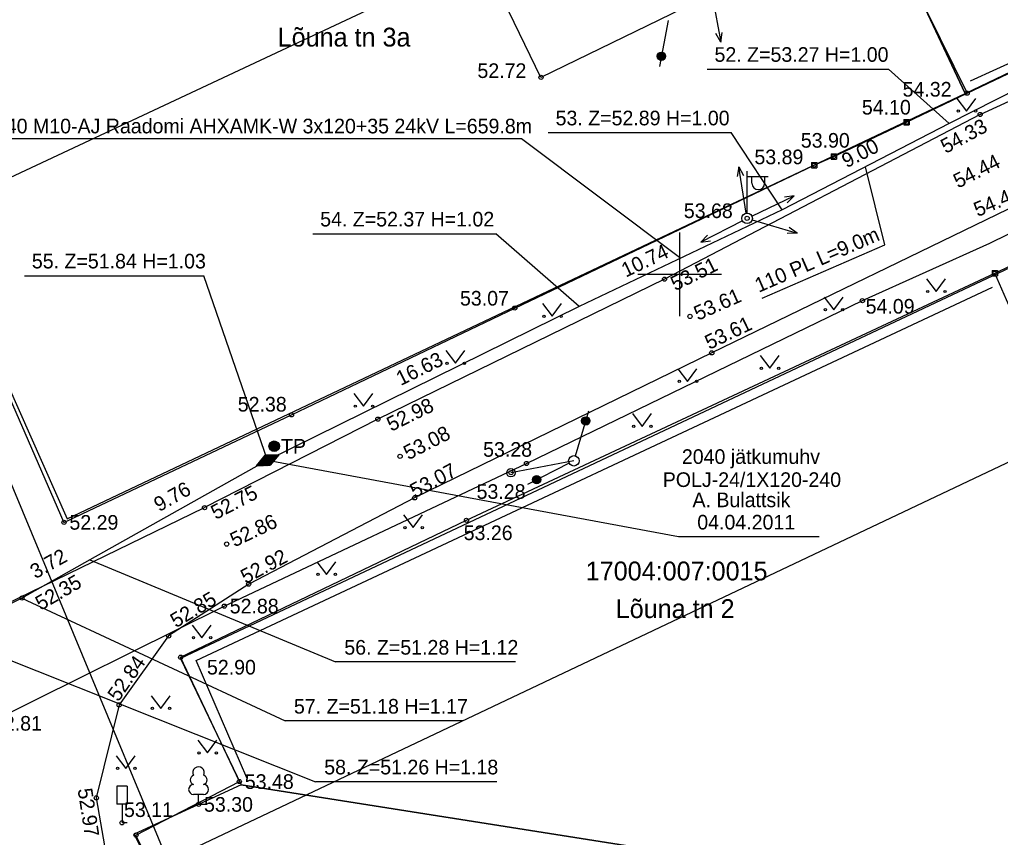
# Model space of a CAD drawing. Extents: x 642747 to 644424, y 6457048 to 6458238.
# Drawn here: x 643818.42 to 643865.35, y 6457573.06 to 6457612.18 of the extents above; entities that cross this region are included whole.
import ezdxf

# ---------------------------------------------------------------- set-up
doc = ezdxf.new("R2010")
doc.units = 0
for name, color, linetype in [('ABIJOONIS', 7, 'Continuous'), ('AED', 7, 'Continuous'), ('HALJASTUS', 7, 'Continuous'), ('HOONE', 7, 'Continuous'), ('JOONSIDE', 7, 'Continuous'), ('KOORDPUNKT', 7, 'Continuous'), ('KORGUS', 7, 'Continuous'), ('KPKAABEL', 7, 'Continuous'), ('KTRASS', 7, 'Continuous'), ('LIIKLUS', 7, 'Continuous'), ('MOOTPIIR', 7, 'Continuous'), ('MPOHULIIN', 7, 'Continuous'), ('PIIR', 7, 'Continuous'), ('POST', 7, 'Continuous'), ('PUU', 7, 'Continuous'), ('SIOHULIIN', 7, 'Continuous'), ('SITRASS', 7, 'Continuous'), ('TEE', 7, 'Continuous'), ('VORK', 7, 'Continuous')]:
    doc.layers.add(name, color=color, linetype=linetype)

msp = doc.modelspace()

# ---------------------------------------------------------------- linework, layer by layer
at = {"layer": 'ABIJOONIS'}
for points in [[(643816.733, 6457606.496), (643842.433, 6457606.496), (643850.05, 6457600.77)], [(643853.945, 6457598.849), (643859.815, 6457601.408), (643858.899, 6457605.144)], [(643830.279, 6457591.107), (643849.945, 6457587.448), (643856.673, 6457587.448)]]:
    msp.add_lwpolyline(points, dxfattribs=at)
at = {"layer": 'AED'}
for p, q in [((643860.735, 6457607.395), (643860.735, 6457607.145)), ((643860.735, 6457607.395), (643860.985, 6457607.395)), ((643860.735, 6457607.145), (643860.985, 6457607.145)), ((643860.985, 6457607.395), (643860.985, 6457607.145)), ((643857.252, 6457605.76), (643857.252, 6457605.51)), ((643857.252, 6457605.76), (643857.502, 6457605.76)), ((643857.502, 6457605.76), (643857.502, 6457605.51)), ((643856.314, 6457605.342), (643856.314, 6457605.092)), ((643856.314, 6457605.342), (643856.564, 6457605.342)), ((643856.314, 6457605.092), (643856.564, 6457605.092)), ((643856.564, 6457605.342), (643856.564, 6457605.092)), ((643857.252, 6457605.51), (643857.502, 6457605.51)), ((643864.958, 6457600.176), (643864.958, 6457599.926)), ((643864.958, 6457600.176), (643865.208, 6457600.176)), ((643864.958, 6457599.926), (643865.208, 6457599.926)), ((643867.365, 6457594.799), (643865.083, 6457600.051)), ((643865.208, 6457600.176), (643865.208, 6457599.926))]:
    msp.add_line(p, q, dxfattribs=at)
for points in [[(643861.822, 6457612.574), (643863.757, 6457608.659), (643878.812, 6457615.836), (643879.918, 6457616.353), (643883.479, 6457617.962)], [(643865.083, 6457600.051), (643868.028, 6457601.433), (643891.175, 6457612.475), (643903.211, 6457617.963)], [(643813.028, 6457615.84), (643810.323, 6457611.698), (643815.123, 6457600.51), (643820.539, 6457588.129), (643831.427, 6457593.27), (643842.111, 6457598.383), (643856.439, 6457605.217), (643857.377, 6457605.635), (643860.86, 6457607.27), (643863.757, 6457608.659)], [(643828.932, 6457575.729), (643826.121, 6457581.679), (643839.798, 6457588.228), (643865.083, 6457600.051)], [(643829.938, 6457561.161), (643823.985, 6457573.169), (643828.932, 6457575.729)]]:
    msp.add_lwpolyline(points, dxfattribs=at)
at = {"layer": 'HALJASTUS'}
for p, q in [((643878.552, 6457615.933), (643863.897, 6457609.235)), ((643863.27, 6457608.411), (643863.733, 6457607.804)), ((643863.733, 6457607.804), (643864.179, 6457608.411)), ((643861.809, 6457599.78), (643862.272, 6457599.173)), ((643862.272, 6457599.173), (643862.718, 6457599.78)), ((643843.441, 6457598.594), (643843.905, 6457597.987)), ((643843.905, 6457597.987), (643844.35, 6457598.594)), ((643856.915, 6457598.908), (643857.378, 6457598.301)), ((643857.378, 6457598.301), (643857.824, 6457598.908)), ((643838.809, 6457596.348), (643839.273, 6457595.741)), ((643839.273, 6457595.741), (643839.718, 6457596.348)), ((643853.855, 6457596.111), (643854.318, 6457595.504)), ((643854.318, 6457595.504), (643854.764, 6457596.111)), ((643849.921, 6457595.477), (643850.384, 6457594.871)), ((643850.384, 6457594.871), (643850.83, 6457595.477)), ((643834.416, 6457594.293), (643834.879, 6457593.687)), ((643834.879, 6457593.687), (643835.325, 6457594.293)), ((643847.739, 6457593.329), (643848.202, 6457592.722)), ((643848.202, 6457592.722), (643848.648, 6457593.329)), ((643836.792, 6457588.488), (643837.255, 6457587.881)), ((643837.255, 6457587.881), (643837.701, 6457588.488)), ((643832.637, 6457586.242), (643833.1, 6457585.636)), ((643833.1, 6457585.636), (643833.546, 6457586.242)), ((643826.673, 6457583.219), (643827.137, 6457582.612)), ((643827.137, 6457582.612), (643827.582, 6457583.219)), ((643824.705, 6457579.835), (643825.168, 6457579.228)), ((643825.168, 6457579.228), (643825.614, 6457579.835)), ((643826.943, 6457577.705), (643827.406, 6457577.098)), ((643827.406, 6457577.098), (643827.852, 6457577.705)), ((643823.041, 6457576.968), (643823.504, 6457576.361)), ((643823.504, 6457576.361), (643823.95, 6457576.968))]:
    msp.add_line(p, q, dxfattribs=at)
msp.add_lwpolyline([(643829.285, 6457575.914), (643826.869, 6457581.513), (643864.976, 6457599.384)], dxfattribs=at)
for centre in [(643863.332, 6457607.804), (643864.161, 6457607.804), (643861.871, 6457599.173), (643862.7, 6457599.173), (643843.503, 6457597.987), (643844.332, 6457597.987), (643856.977, 6457598.301), (643857.806, 6457598.301), (643838.871, 6457595.741), (643839.7, 6457595.741), (643853.917, 6457595.504), (643854.746, 6457595.504), (643849.983, 6457594.871), (643850.812, 6457594.871), (643834.478, 6457593.687), (643835.307, 6457593.687), (643847.801, 6457592.722), (643848.63, 6457592.722), (643836.854, 6457587.881), (643837.683, 6457587.881), (643832.699, 6457585.636), (643833.528, 6457585.636), (643826.736, 6457582.612), (643827.564, 6457582.612), (643824.767, 6457579.228), (643825.596, 6457579.228), (643827.005, 6457577.098), (643827.834, 6457577.098), (643823.103, 6457576.361), (643823.932, 6457576.361)]:
    msp.add_circle(centre, 0.055, dxfattribs=at)
at = {"layer": 'HOONE'}
msp.add_lwpolyline([(643852.233, 6457621.198), (643853.69, 6457618.146), (643850.68, 6457616.709), (643852.137, 6457613.657), (643850.16, 6457612.713), (643843.365, 6457609.415), (643841.578, 6457613.097)], dxfattribs=at)
at = {"layer": 'KOORDPUNKT'}
for p, q in [((643851.319, 6457609.811), (643859.998, 6457609.811)), ((643862.896, 6457607.211), (643859.998, 6457609.811)), ((643843.714, 6457606.772), (643852.463, 6457606.772)), ((643854.902, 6457603.076), (643852.463, 6457606.772)), ((643832.449, 6457601.934), (643841.198, 6457601.934)), ((643845.198, 6457598.463), (643841.198, 6457601.934)), ((643818.652, 6457599.927), (643827.227, 6457599.927)), ((643830.279, 6457591.107), (643827.227, 6457599.927)), ((643821.771, 6457586.329), (643833.533, 6457581.451)), ((643818.529, 6457584.508), (643831.123, 6457578.631)), ((643814.969, 6457582.717), (643832.573, 6457575.723)), ((643842.142, 6457581.451), (643833.533, 6457581.451)), ((643839.628, 6457578.631), (643831.123, 6457578.631)), ((643841.253, 6457575.723), (643832.573, 6457575.723))]:
    msp.add_line(p, q, dxfattribs=at)
for points in [[(643862.896, 6457607.211), (643862.896, 6457607.211), (643862.896, 6457607.211)], [(643854.902, 6457603.076), (643854.902, 6457603.076), (643854.902, 6457603.076)], [(643845.198, 6457598.463), (643845.198, 6457598.463), (643845.198, 6457598.463)], [(643830.279, 6457591.107), (643830.279, 6457591.107), (643830.279, 6457591.107)], [(643821.771, 6457586.329), (643821.771, 6457586.329), (643821.771, 6457586.329)], [(643818.529, 6457584.508), (643818.529, 6457584.508), (643818.529, 6457584.508)]]:
    msp.add_lwpolyline(points, dxfattribs=at)
at = {"layer": 'KORGUS'}
for centre in [(643843.365, 6457609.415), (643863.757, 6457608.659), (643864.382, 6457607.643), (643860.86, 6457607.27), (643857.377, 6457605.635), (643856.439, 6457605.217), (643853.23, 6457602.673), (643865.083, 6457600.051), (643849.276, 6457599.763), (643858.747, 6457598.735), (643842.111, 6457598.383), (643850.497, 6457597.981), (643851.537, 6457596.237), (643831.427, 6457593.27), (643835.56, 6457593.069), (643836.623, 6457591.289), (643842.673, 6457590.948), (643841.927, 6457590.503), (643837.319, 6457589.3), (643827.265, 6457588.833), (643820.539, 6457588.129), (643839.798, 6457588.228), (643828.324, 6457587.09), (643829.38, 6457585.174), (643818.529, 6457584.508), (643828.211, 6457584.123), (643825.548, 6457582.694), (643826.121, 6457581.679), (643823.177, 6457579.399), (643828.932, 6457575.729), (643822.086, 6457574.949), (643826.98, 6457574.637), (643823.317, 6457573.755), (643823.985, 6457573.169)]:
    msp.add_circle(centre, 0.1, dxfattribs=at)
at = {"layer": 'KPKAABEL'}
for p, q in [((643829.747, 6457590.841), (643830.16, 6457591.348)), ((643829.876, 6457591), (643830.077, 6457590.851)), ((643829.892, 6457591.019), (643830.118, 6457590.853)), ((643829.908, 6457591.039), (643830.159, 6457590.854)), ((643829.924, 6457591.058), (643830.199, 6457590.855)), ((643829.939, 6457591.077), (643830.24, 6457590.856)), ((643829.955, 6457591.097), (643830.28, 6457590.857)), ((643829.971, 6457591.116), (643830.321, 6457590.859)), ((643829.987, 6457591.135), (643830.361, 6457590.86)), ((643830.003, 6457591.155), (643830.4, 6457590.862)), ((643830.019, 6457591.174), (643830.416, 6457590.881)), ((643830.034, 6457591.194), (643830.432, 6457590.901)), ((643830.05, 6457591.213), (643830.448, 6457590.92)), ((643830.066, 6457591.232), (643830.464, 6457590.939)), ((643830.082, 6457591.252), (643830.48, 6457590.959)), ((643830.098, 6457591.271), (643830.495, 6457590.978)), ((643830.113, 6457591.291), (643830.511, 6457590.998)), ((643830.129, 6457591.31), (643830.527, 6457591.017)), ((643830.145, 6457591.329), (643830.543, 6457591.036)), ((643830.813, 6457591.367), (643830.16, 6457591.348)), ((643830.163, 6457591.348), (643830.559, 6457591.056)), ((643830.203, 6457591.349), (643830.575, 6457591.075)), ((643830.244, 6457591.35), (643830.59, 6457591.095)), ((643830.284, 6457591.351), (643830.606, 6457591.114)), ((643830.325, 6457591.352), (643830.622, 6457591.133)), ((643830.365, 6457591.354), (643830.638, 6457591.153)), ((643830.813, 6457591.367), (643830.4, 6457590.861)), ((643830.406, 6457591.355), (643830.654, 6457591.172)), ((643830.446, 6457591.356), (643830.67, 6457591.192)), ((643830.487, 6457591.357), (643830.685, 6457591.211)), ((643830.527, 6457591.359), (643830.701, 6457591.23)), ((643830.568, 6457591.36), (643830.717, 6457591.25)), ((643830.608, 6457591.361), (643830.733, 6457591.269)), ((643830.649, 6457591.362), (643830.749, 6457591.288)), ((643830.689, 6457591.363), (643830.764, 6457591.308)), ((643830.73, 6457591.365), (643830.78, 6457591.327)), ((643830.77, 6457591.366), (643830.796, 6457591.347)), ((643830.811, 6457591.367), (643830.812, 6457591.366)), ((643829.747, 6457590.841), (643830.4, 6457590.861)), ((643829.765, 6457590.864), (643829.794, 6457590.843)), ((643829.781, 6457590.883), (643829.834, 6457590.844)), ((643829.797, 6457590.903), (643829.875, 6457590.845)), ((643829.813, 6457590.922), (643829.915, 6457590.847)), ((643829.829, 6457590.942), (643829.956, 6457590.848)), ((643829.844, 6457590.961), (643829.996, 6457590.849)), ((643829.86, 6457590.98), (643830.037, 6457590.85))]:
    msp.add_line(p, q, dxfattribs=at)
for points in [[(643871.792, 6457611.727), (643862.896, 6457607.211), (643854.902, 6457603.076), (643845.198, 6457598.463), (643830.279, 6457591.107), (643821.771, 6457586.329), (643818.529, 6457584.508), (643814.969, 6457582.717), (643809.094, 6457580.741), (643805.91, 6457580.287), (643796.342, 6457575.552), (643785.796, 6457571.037), (643776.843, 6457566.645)], [(643862.896, 6457607.211), (643854.902, 6457603.076)], [(643821.771, 6457586.329), (643818.529, 6457584.508), (643814.969, 6457582.717), (643809.094, 6457580.741), (643805.91, 6457580.287)]]:
    msp.add_lwpolyline(points, dxfattribs=at)
at = {"layer": 'KTRASS'}
msp.add_line((643826.248, 6457570.158), (643816.291, 6457594.12), dxfattribs=at)
at = {"layer": 'LIIKLUS'}
for p, q in [((643823.067, 6457575.505), (643823.067, 6457574.655)), ((643823.567, 6457575.505), (643823.067, 6457575.505)), ((643823.567, 6457575.505), (643823.567, 6457574.655)), ((643823.567, 6457574.655), (643823.067, 6457574.655)), ((643823.317, 6457574.655), (643823.317, 6457573.755)), ((643823.567, 6457573.755), (643823.317, 6457573.755))]:
    msp.add_line(p, q, dxfattribs=at)
at = {"layer": 'MOOTPIIR'}
msp.add_lwpolyline([(643525.446, 6457467.559), (643537.447, 6457435.458), (643944.848, 6457628.51), (644046.626, 6457529.09), (644067.022, 6457529.09), (644138.408, 6457598.401), (644075.1, 6457775.215), (644046.02, 6457752.582), (644092.466, 6457611.94), (644070.657, 6457576.375), (644041.981, 6457570.717), (643942.223, 6457662.862)], close=True, dxfattribs=at)
at = {"layer": 'MPOHULIIN'}
for p, q in [((643851.558, 6457613.306), (643851.964, 6457611.093)), ((643851.964, 6457611.093), (643851.736, 6457611.511)), ((643851.964, 6457611.093), (643852.03, 6457611.564)), ((643852.837, 6457605.141), (643852.759, 6457604.672)), ((643852.837, 6457605.141), (643853.054, 6457604.719)), ((643853.191, 6457602.92), (643852.837, 6457605.141)), ((643853.456, 6457602.78), (643855.486, 6457603.751)), ((643855.486, 6457603.751), (643855.014, 6457603.692)), ((643855.486, 6457603.751), (643855.142, 6457603.422)), ((643853.008, 6457602.558), (643851.007, 6457601.53)), ((643853.47, 6457602.602), (643855.629, 6457601.969)), ((643851.007, 6457601.53), (643851.34, 6457601.868)), ((643855.629, 6457601.969), (643855.154, 6457601.954)), ((643855.629, 6457601.969), (643855.238, 6457602.24)), ((643851.007, 6457601.53), (643851.477, 6457601.603))]:
    msp.add_line(p, q, dxfattribs=at)
at = {"layer": 'PIIR'}
for points in [[(643889.53, 6457621.03), (643855.16, 6457693.26), (643829.6, 6457681.02), (643840.45, 6457657.96), (643863.66, 6457608.64)], [(643820.69, 6457588.29), (643863.66, 6457608.64), (643840.45, 6457657.96), (643810.37, 6457611.54)], [(643829.02, 6457575.57), (643868.83, 6457569.29), (643917.77, 6457562.51), (643924.07, 6457589.85), (643898.41, 6457594.93), (643903.01, 6457617.85), (643826.12, 6457581.61)], [(643823.9, 6457573.21), (643846.95, 6457526.28), (643871.69, 6457538.12), (643868.83, 6457569.29), (643829.02, 6457575.57)]]:
    msp.add_lwpolyline(points, close=True, dxfattribs=at)
at = {"layer": 'POST'}
for p, q in [((643853.23, 6457602.923), (643853.23, 6457604.923)), ((643853.23, 6457604.673), (643854.23, 6457604.673)), ((643853.457, 6457604.352), (643853.457, 6457604.673)), ((643854.07, 6457604.352), (643854.07, 6457604.673)), ((643853.23, 6457602.673), (643853.23, 6457602.673)), ((643844.94, 6457591.073), (643841.927, 6457590.503))]:
    msp.add_line(p, q, dxfattribs=at)
for centre, radius in [((643853.23, 6457602.673), 0.25), ((643830.599, 6457591.772), 0.25), ((643830.599, 6457591.772), 0.225), ((643830.599, 6457591.772), 0.2), ((643830.599, 6457591.772), 0.175), ((643830.599, 6457591.772), 0.15), ((643830.599, 6457591.772), 0.125), ((643830.599, 6457591.772), 0.1), ((643830.599, 6457591.772), 0.075), ((643830.599, 6457591.772), 0.05), ((643830.599, 6457591.772), 0.025), ((643844.94, 6457591.073), 0.25), ((643841.927, 6457590.503), 0.2)]:
    msp.add_circle(centre, radius, dxfattribs=at)
msp.add_arc((643853.763, 6457604.352), 0.306, 180, 0, dxfattribs=at)
at = {"layer": 'PUU'}
for p, q in [((643827.22, 6457575.112), (643826.74, 6457575.112)), ((643826.98, 6457574.637), (643826.98, 6457575.112)), ((643827.36, 6457574.637), (643826.98, 6457574.637))]:
    msp.add_line(p, q, dxfattribs=at)
for centre, radius, start, end in [((643826.81, 6457575.81), 0.233, 109.0217, 253.1415), ((643826.98, 6457576.157), 0.277, 332.5799, 207.4201), ((643827.15, 6457575.81), 0.233, 286.8508, 70.9859), ((643826.742, 6457575.35), 0.238, 90.0016, 269.3953), ((643827.217, 6457575.35), 0.238, 270.6047, 89.9984)]:
    msp.add_arc(centre, radius, start, end, dxfattribs=at)
at = {"layer": 'SIOHULIIN'}
for p, q in [((643849.448, 6457612.144), (643849.039, 6457609.941)), ((643845.011, 6457591.312), (643845.65, 6457593.46)), ((643844.717, 6457590.96), (643842.717, 6457589.948))]:
    msp.add_line(p, q, dxfattribs=at)
for centre, radius in [((643849.129, 6457610.429), 0.199), ((643849.129, 6457610.429), 0.19), ((643849.129, 6457610.429), 0.18), ((643849.129, 6457610.429), 0.171), ((643849.129, 6457610.429), 0.162), ((643849.129, 6457610.429), 0.152), ((643849.129, 6457610.429), 0.143), ((643849.129, 6457610.429), 0.133), ((643849.129, 6457610.429), 0.124), ((643849.129, 6457610.429), 0.114), ((643849.129, 6457610.429), 0.105), ((643849.129, 6457610.429), 0.0953), ((643849.129, 6457610.429), 0.0858), ((643849.129, 6457610.429), 0.0763), ((643849.129, 6457610.429), 0.0669), ((643849.129, 6457610.429), 0.0574), ((643849.129, 6457610.429), 0.0479), ((643849.129, 6457610.429), 0.0385), ((643849.129, 6457610.429), 0.029), ((643849.129, 6457610.429), 0.0195), ((643849.129, 6457610.429), 0.0101), ((643849.129, 6457610.429), 0.00061), ((643845.509, 6457592.985), 0.199), ((643845.509, 6457592.985), 0.19), ((643845.509, 6457592.985), 0.18), ((643845.509, 6457592.985), 0.171), ((643845.509, 6457592.985), 0.162), ((643845.509, 6457592.985), 0.152), ((643845.509, 6457592.985), 0.143), ((643845.509, 6457592.985), 0.133), ((643845.509, 6457592.985), 0.124), ((643845.509, 6457592.985), 0.114), ((643845.509, 6457592.985), 0.105), ((643845.509, 6457592.985), 0.0953), ((643845.509, 6457592.985), 0.0858), ((643845.509, 6457592.985), 0.0763), ((643845.509, 6457592.985), 0.0669), ((643845.509, 6457592.985), 0.0574), ((643845.509, 6457592.985), 0.0479), ((643845.509, 6457592.985), 0.0385), ((643845.509, 6457592.985), 0.029), ((643845.509, 6457592.985), 0.0195), ((643845.509, 6457592.985), 0.0101), ((643845.509, 6457592.985), 0.00061), ((643843.16, 6457590.172), 0.199), ((643843.16, 6457590.172), 0.19), ((643843.16, 6457590.172), 0.18), ((643843.16, 6457590.172), 0.171), ((643843.16, 6457590.172), 0.162), ((643843.16, 6457590.172), 0.152), ((643843.16, 6457590.172), 0.143), ((643843.16, 6457590.172), 0.133), ((643843.16, 6457590.172), 0.124), ((643843.16, 6457590.172), 0.114), ((643843.16, 6457590.172), 0.105), ((643843.16, 6457590.172), 0.0953), ((643843.16, 6457590.172), 0.0858), ((643843.16, 6457590.172), 0.0763), ((643843.16, 6457590.172), 0.0669), ((643843.16, 6457590.172), 0.0574), ((643843.16, 6457590.172), 0.0479), ((643843.16, 6457590.172), 0.0385), ((643843.16, 6457590.172), 0.029), ((643843.16, 6457590.172), 0.0195), ((643843.16, 6457590.172), 0.0101), ((643843.16, 6457590.172), 0.00061)]:
    msp.add_circle(centre, radius, dxfattribs=at)
at = {"layer": 'SITRASS'}
msp.add_lwpolyline([(643812.026, 6457576.221), (643816.881, 6457578.515), (643828.211, 6457584.123), (643842.673, 6457590.948), (643858.747, 6457598.735), (643864.842, 6457601.479), (643876.315, 6457607.122), (643881.915, 6457609.804), (643890.98, 6457613.883), (643903.517, 6457619.568), (643924.826, 6457629.194), (643927.523, 6457629.75), (643928.08, 6457629.511), (643929.114, 6457628.139)], dxfattribs=at)
at = {"layer": 'TEE'}
for points in [[(643864.382, 6457607.643), (643873.126, 6457611.666), (643889.208, 6457619.122), (643896.548, 6457622.57)], [(643864.382, 6457607.643), (643849.276, 6457599.763), (643835.56, 6457593.069), (643827.265, 6457588.833)], [(643866.74, 6457603.613), (643851.537, 6457596.237), (643837.319, 6457589.3), (643829.38, 6457585.174), (643825.548, 6457582.694), (643823.177, 6457579.399), (643822.086, 6457574.949), (643822.835, 6457570.636)], [(643804.329, 6457598.654), (643807.202, 6457592.783), (643812.117, 6457583.784), (643813.61, 6457582.212), (643827.265, 6457588.833)]]:
    msp.add_lwpolyline(points, dxfattribs=at)
at = {"layer": 'VORK'}
for p, q in [((643850, 6457602), (643850, 6457598)), ((643848, 6457600), (643852, 6457600))]:
    msp.add_line(p, q, dxfattribs=at)

# ---------------------------------------------------------------- texts
at = {"layer": 'ABIJOONIS'}
for s, p in [('2040 M10-AJ Raadomi AHXAMK-W 3x120+35 24kV L=659.8m', (643816.713, 6457606.738)), ('2040 jätkumuhv', (643850.108, 6457590.925)), ('POLJ-24/1X120-240', (643849.193, 6457589.822)), ('A. Bulattsik', (643850.616, 6457588.856)), ('04.04.2011', (643850.845, 6457587.788))]:
    msp.add_text(s, height=0.7, dxfattribs=at).set_placement(p)
msp.add_text('110 PL L=9.0m', height=0.7, rotation=23.4798, dxfattribs=at).set_placement((643853.786, 6457599.108))
at = {"layer": 'JOONSIDE'}
for s, rotation, p in [('9.00', 27.3505, (643857.989, 6457605.063)), ('10.74', 25.4254, (643847.425, 6457599.834)), ('16.63', 26.2462, (643836.652, 6457594.65)), ('9.76', 29.3193, (643825.093, 6457588.614)), ('3.72', 29.3193, (643819.171, 6457585.406))]:
    msp.add_text(s, height=0.7, rotation=rotation, dxfattribs=at).set_placement(p)
at = {"layer": 'KOORDPUNKT'}
for s, p in [('52. Z=53.27 H=1.00', (643851.669, 6457610.161)), ('53. Z=52.89 H=1.00', (643844.064, 6457607.122)), ('54. Z=52.37 H=1.02', (643832.799, 6457602.284)), ('55. Z=51.84 H=1.03', (643819.002, 6457600.277)), ('56. Z=51.28 H=1.12', (643833.953, 6457581.801)), ('57. Z=51.18 H=1.17', (643831.543, 6457578.981)), ('58. Z=51.26 H=1.18', (643832.993, 6457576.073))]:
    msp.add_text(s, height=0.7, dxfattribs=at).set_placement(p)
at = {"layer": 'KORGUS'}
for s, p in [(' 52.72', (643840.064, 6457609.387)), (' 54.32', (643860.411, 6457608.497)), (' 54.10', (643858.462, 6457607.637)), (' 53.90', (643855.54, 6457606.054)), (' 53.89', (643853.319, 6457605.261)), (' 53.68', (643849.941, 6457602.685)), (' 53.07', (643839.229, 6457598.5)), (' 54.09', (643858.641, 6457598.115)), (' 52.38', (643828.595, 6457593.43)), (' 53.28', (643840.336, 6457591.268)), (' 53.28', (643840.024, 6457589.254)), (' 52.29', (643820.539, 6457587.779)), (' 53.26', (643839.405, 6457587.28)), (' 52.88', (643828.211, 6457583.773)), (' 52.90', (643827.121, 6457580.851)), (' 52.81', (643816.881, 6457578.165)), (' 53.48', (643828.932, 6457575.379)), (' 53.11', (643823.15, 6457574.035)), (' 53.30', (643826.98, 6457574.287))]:
    msp.add_text(s, height=0.7, dxfattribs=at).set_placement(p)
for s, rotation, p in [(' 54.33', 28.288, (643862.504, 6457605.629)), (' 54.44', 26.8683, (643863.093, 6457603.976)), (' 54.40', 22.8267, (643864.018, 6457602.63)), (' 53.51', 26.2799, (643849.556, 6457599.069)), (' 53.61', 23.9407, (643850.639, 6457597.662)), (' 53.61', 25.6218, (643851.185, 6457596.264)), (' 52.98', 26.0356, (643835.967, 6457592.345)), (' 53.08', 27.0821, (643836.783, 6457590.977)), (' 53.07', 28.1905, (643837.105, 6457589.152)), (' 52.75', 27.4161, (643827.57, 6457588.119)), (' 52.86', 25.3383, (643828.464, 6457586.817)), (' 52.92', 27.9681, (643829.002, 6457585.048)), ('52.35', 30.1708, (643819.428, 6457583.893)), (' 52.85', 30.7502, (643825.671, 6457582.929)), (' 52.84', 55.1683, (643822.994, 6457579.3)), (' 52.97', 278.6476, (643821.15, 6457575.619))]:
    msp.add_text(s, height=0.7, rotation=rotation, dxfattribs=at).set_placement(p)
at = {"layer": 'PIIR'}
for s, p in [('Lõuna tn 3a', (643830.763, 6457610.892)), ('17004:007:0015', (643845.506, 6457585.353)), ('Lõuna tn 2', (643846.941, 6457583.553))]:
    msp.add_text(s, height=0.9, dxfattribs=at).set_placement(p)
at = {"layer": 'POST'}
msp.add_text('TP', height=0.7, dxfattribs=at).set_placement((643830.925, 6457591.419))

doc.saveas('drawing.dxf')
